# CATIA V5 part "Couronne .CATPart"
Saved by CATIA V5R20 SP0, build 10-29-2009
Part number: Couronne 
Bounding box of the stored display mesh (mm): x -23.493 to 23.493, y -23.493 to 23.493, z -1.5 to 1.5
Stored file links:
  G:\Khaled_CFAO_2011\SIL\SIL_GR1\blaboucarri\Khaled\CAD_CATIA\Couronne .CATPart
  C:\Users\Béatrice\Documents\IFMA\Cours\Semestre 3\CFAO\Think motion parapluie\Fina\Coulisseau et couronne.CATProduct
  G:\Khaled_CFAO_2011\SIL\SIL_GR1\blaboucarri\Khaled\CAD_CATIA\piece 4.CATPart
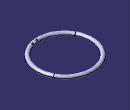
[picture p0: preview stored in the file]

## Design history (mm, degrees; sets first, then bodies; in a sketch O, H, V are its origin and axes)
Parameters
  `rayon couronne` = 22 mm
  `rayon section` = 1.5 mm
  LENGTH = 0 mm
Set1
  Plane1: linked copy from another document
Body1 (main body)
  Sketch1 on xy-plane, origin (0, 0, 0), H (1, 0, 0), V (0, 1, 0)
    circle A1 centre (0, 0) radius 22
    point P1 (22, 0)
    radius A1 = 22 {= `rayon couronne`}
    coincidence: A1 P1, P1 H
  Sketch2 on zx-plane, origin (0, 0, 0), H (-1, 0, 0), V (0, 0, 1)
    circle A1 centre (-22, 0) radius 1.5
    point P1 (-22, 0)
    reference projected line E1 (-22, 0) -> (22, 0) from Sketch1.A1
    radius A1 = 1.5 {= `rayon section`}
    coincidence: P1 H, E1 P1
  Shaft1: profile Sketch2, axis Sketch2.V, angle 360
  Point1: type OnCurve, Support Sketch1, RefPoint {extremum Reference Sketch1, Direction (1, 2, 3)}, Length 82.5
  DatumCurve1
  Line1: type PtDir, RefPoint Point1, Direction DatumCurve1, Start -2, End 2
  Plane2: type Offset, RefPlane Plane1, Offset 0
